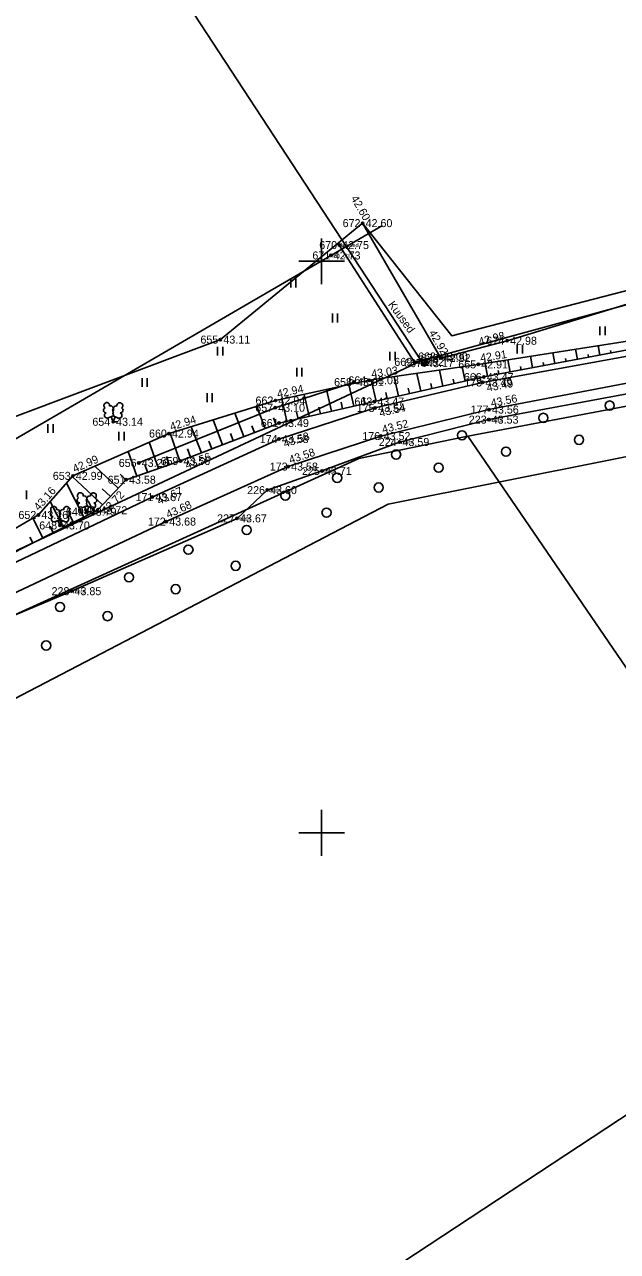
# Model space of a CAD drawing. Extents: x 505800 to 507326, y 6540058 to 6542128.
# Drawn here: x 506424 to 506475.9, y 6540313.4 to 6540420.7 of the extents above; entities that cross this region are included whole.
import ezdxf

# ---------------------------------------------------------------- set-up
doc = ezdxf.new("R2010")
doc.units = 0
for name, color, linetype in [('AED', 7, 'Continuous'), ('HALJASTUS', 7, 'Continuous'), ('KORGUS-EH2000', 7, 'Continuous'), ('MAAMUDEL', 7, 'Continuous'), ('MOOTKORG-EH2000', 7, 'Continuous'), ('MOOTMPUNKT', 7, 'Continuous'), ('MOOTNR', 7, 'Continuous'), ('MOOTPIIR', 7, 'Continuous'), ('MPOHULIIN', 7, 'Continuous'), ('PIIR', 7, 'Continuous'), ('POST', 7, 'Continuous'), ('PUU', 7, 'Continuous'), ('RELJEEF', 7, 'Continuous'), ('TEE', 7, 'Continuous'), ('VORK', 7, 'Continuous')]:
    doc.layers.add(name, color=color, linetype=linetype)

msp = doc.modelspace()

# ---------------------------------------------------------------- linework, layer by layer
at = {"layer": 'AED'}
msp.add_lwpolyline([(506555.48, 6540425.13), (506557.14, 6540420.8), (506466.24, 6540393.05), (506460.43, 6540391.54), (506453.59, 6540403.33)], dxfattribs=at)
at = {"layer": 'HALJASTUS'}
for p, q in [((506447.3, 6540398.46), (506447.3, 6540397.7)), ((506447.75, 6540398.46), (506447.75, 6540397.7)), ((506450.94, 6540395.42), (506450.94, 6540394.65)), ((506451.39, 6540395.42), (506451.39, 6540394.65)), ((506474.36, 6540394.29), (506474.36, 6540393.53)), ((506474.82, 6540394.29), (506474.82, 6540393.53)), ((506440.89, 6540392.53), (506440.89, 6540391.77)), ((506441.35, 6540392.53), (506441.35, 6540391.77)), ((506467.11, 6540392.69), (506467.11, 6540391.93)), ((506467.57, 6540392.69), (506467.57, 6540391.93)), ((506455.98, 6540392.09), (506455.98, 6540391.33)), ((506456.44, 6540392.09), (506456.44, 6540391.33)), ((506447.82, 6540390.69), (506447.82, 6540389.93)), ((506448.27, 6540390.69), (506448.27, 6540389.93)), ((506434.28, 6540389.77), (506434.28, 6540389.01)), ((506434.74, 6540389.77), (506434.74, 6540389.01)), ((506439.97, 6540388.45), (506439.97, 6540387.68)), ((506440.42, 6540388.45), (506440.42, 6540387.68)), ((506426.04, 6540385.76), (506426.04, 6540385)), ((506426.49, 6540385.76), (506426.49, 6540385)), ((506432.24, 6540385.08), (506432.24, 6540384.32)), ((506432.7, 6540385.08), (506432.7, 6540384.32)), ((506424.17, 6540379.95), (506424.17, 6540379.19))]:
    msp.add_line(p, q, dxfattribs=at)
for points in [[(506413.94, 6540356.96), (506411.03, 6540361.54), (506411.48, 6540364.07), (506416.66, 6540366.32), (506428.11, 6540371.14), (506442.6, 6540377.51), (506445.23, 6540379.98), (506450.03, 6540381.66), (506456.82, 6540384.19), (506464.63, 6540386.15), (506480.51, 6540389.11), (506500.86, 6540392.97), (506504.84, 6540391.73), (506512.52, 6540393.4), (506515.37, 6540396.65), (506532.17, 6540402.94), (506544.15, 6540408.03), (506554.03, 6540411.41), (506558.08, 6540412.38), (506561.96, 6540411.87), (506565.62, 6540410.41), (506569.33, 6540407.84)], [(506451.54, 6540401.42), (506458.11, 6540391.2), (506460.19, 6540391.67)], [(506452.84, 6540389.43), (506445.94, 6540387.19), (506433.99, 6540382.36)]]:
    msp.add_lwpolyline(points, dxfattribs=at)
for centre in [(506475.22, 6540387.38), (506469.41, 6540386.3), (506462.29, 6540384.78), (506472.53, 6540384.38), (506456.52, 6540383.1), (506466.13, 6540383.34), (506460.24, 6540381.94), (506451.36, 6540381.06), (506446.83, 6540379.49), (506455, 6540380.21), (506450.43, 6540378.01), (506443.43, 6540376.49), (506438.34, 6540374.77), (506442.47, 6540373.36), (506433.14, 6540372.36), (506437.22, 6540371.32), (506427.09, 6540369.76), (506431.26, 6540368.96), (506425.89, 6540366.39)]:
    msp.add_circle(centre, 0.4, dxfattribs=at)
at = {"layer": 'KORGUS-EH2000'}
for centre in [(506453.59, 6540403.33), (506451.54, 6540401.42), (506450.8, 6540400.51), (506441.14, 6540393.15), (506466.24, 6540393.05), (506460.19, 6540391.67), (506460.43, 6540391.54), (506458.11, 6540391.2), (506458.97, 6540391.09), (506463.71, 6540390.98), (506452.84, 6540389.43), (506454.16, 6540389.59), (506464.09, 6540389.4), (506464.2, 6540389.88), (506445.94, 6540387.19), (506445.96, 6540387.82), (506454.62, 6540387.73), (506454.68, 6540387.17), (506464.63, 6540386.15), (506464.65, 6540387.03), (506431.75, 6540385.96), (506436.64, 6540384.93), (506446.28, 6540385.85), (506446.26, 6540384.45), (506455.17, 6540384.71), (506456.82, 6540384.19), (506433.99, 6540382.36), (506437.65, 6540382.53), (506447.07, 6540382.04), (506428.22, 6540381.23), (506432.88, 6540380.89), (506450.03, 6540381.66), (506445.23, 6540379.98), (506435.18, 6540379.37), (506425.21, 6540377.81), (506429.44, 6540378.09), (506430.38, 6540378.22), (506442.6, 6540377.51), (506427.1, 6540376.89), (506436.4, 6540377.23), (506428.11, 6540371.14)]:
    msp.add_circle(centre, 0.1, dxfattribs=at)
at = {"layer": 'MOOTMPUNKT'}
for centre in [(506453.59, 6540403.33), (506451.54, 6540401.42), (506450.8, 6540400.51), (506441.14, 6540393.15), (506466.24, 6540393.05), (506460.19, 6540391.67), (506460.43, 6540391.54), (506458.11, 6540391.2), (506458.97, 6540391.09), (506463.71, 6540390.98), (506452.84, 6540389.43), (506454.16, 6540389.59), (506464.09, 6540389.4), (506464.2, 6540389.88), (506445.94, 6540387.19), (506445.96, 6540387.82), (506454.62, 6540387.73), (506454.68, 6540387.17), (506464.63, 6540386.15), (506464.65, 6540387.03), (506431.75, 6540385.96), (506436.64, 6540384.93), (506446.28, 6540385.85), (506446.26, 6540384.45), (506455.17, 6540384.71), (506456.82, 6540384.19), (506433.99, 6540382.36), (506437.65, 6540382.53), (506447.07, 6540382.04), (506428.22, 6540381.23), (506432.88, 6540380.89), (506450.03, 6540381.66), (506445.23, 6540379.98), (506435.18, 6540379.37), (506425.21, 6540377.81), (506429.44, 6540378.09), (506430.38, 6540378.22), (506442.6, 6540377.51), (506427.1, 6540376.89), (506436.4, 6540377.23), (506428.11, 6540371.14)]:
    msp.add_circle(centre, 0.1, dxfattribs=at)
at = {"layer": 'MOOTPIIR'}
for points in [[(506240.25, 6540270.96), (506245.95, 6540263.86), (506266.13, 6540270.79), (506275.98, 6540276.68), (506285.51, 6540285.66), (506298.84, 6540299.88), (506301.09, 6540304.53), (506297.72, 6540312.74), (506305.02, 6540318.44), (506309.38, 6540311.75), (506312.33, 6540315.18), (506338.03, 6540330.65), (506336.91, 6540340.18), (506347.36, 6540347.55), (506370.89, 6540361.7), (506382.39, 6540366.46), (506390.08, 6540368.87), (506400.57, 6540374.13), (506410.57, 6540381.71), (506441.14, 6540393.15), (506453.59, 6540403.33), (506461.4, 6540393.47), (506495.45, 6540402.28)], [(506495.18, 6540386.6), (506455.81, 6540378.75), (506413.94, 6540356.96), (506411.43, 6540354.11), (506402.31, 6540351.52), (506392, 6540341.5), (506380.9, 6540334.94), (506360.25, 6540322.57), (506353.01, 6540324.95), (506332.13, 6540309.04), (506315.6, 6540297.89), (506301.38, 6540281.9), (506292.83, 6540267.67), (506286.65, 6540264.51), (506248.47, 6540250.07)]]:
    msp.add_lwpolyline(points, dxfattribs=at)
at = {"layer": 'MPOHULIIN'}
msp.add_line((506416.45, 6540380.54), (506455.33, 6540403.12), dxfattribs=at)
at = {"layer": 'PIIR'}
for points in [[(506527.76, 6540505.12), (506563.96, 6540420.02), (506458.7, 6540391.28), (506429.21, 6540436.36), (506427.6, 6540438.79), (506466.35, 6540463.04), (506513.09, 6540491.84), (506518.32, 6540495.02), (506520.1, 6540496.45)], [(506326.14, 6540370.11), (506324.04, 6540375.18), (506354.05, 6540393.57), (506395.54, 6540418.74), (506427.6, 6540438.79), (506429.21, 6540436.36), (506458.7, 6540391.28), (506340.34, 6540335.82)], [(506462.8, 6540384.69), (506497.85, 6540391.32), (506509.27, 6540394.46), (506551.97, 6540410.35), (506558.26, 6540412.17), (506562.23, 6540412.5), (506566.7, 6540411.34), (506570.51, 6540407.87), (506575.14, 6540401.74), (506580.6, 6540391.81), (506495.14, 6540337.45)]]:
    msp.add_lwpolyline(points, close=True, dxfattribs=at)
for points in [[(506215.95, 6540254.34), (506268.55, 6540273.9), (506274.54, 6540277.85), (506304.35, 6540308.95), (506340.34, 6540335.82), (506458.7, 6540391.28), (506563.96, 6540420.02)], [(506497.85, 6540391.32), (506462.8, 6540384.69), (506453.27, 6540382.76), (506413.82, 6540364.84), (506374.55, 6540342.6), (506353.59, 6540332.53), (506318.07, 6540309.28), (506308, 6540301.95), (506281.65, 6540275.05), (506272.39, 6540267.75), (506224.13, 6540249.92)], [(506224.13, 6540249.92), (506272.39, 6540267.75), (506281.65, 6540275.05), (506308, 6540301.95), (506318.07, 6540309.28), (506353.59, 6540332.53), (506374.55, 6540342.6), (506413.82, 6540364.84), (506453.27, 6540382.76), (506462.8, 6540384.69), (506495.14, 6540337.45), (506342.85, 6540237.27), (506260.72, 6540195.9), (506215.68, 6540179.69)]]:
    msp.add_lwpolyline(points, dxfattribs=at)
at = {"layer": 'POST'}
msp.add_line((506458.79, 6540390.91), (506459.15, 6540391.27), dxfattribs=at)
msp.add_circle((506458.97, 6540391.09), 0.25, dxfattribs=at)
for radius, start, end in [(0.225, 224.8541, 45.0356), (0.2, 224.8427, 45.047), (0.175, 224.8281, 45.0616), (0.15, 224.8087, 45.081), (0.125, 224.7814, 45.1083), (0.1, 224.7406, 45.1491), (0.075, 224.6725, 45.2172), (0.05, 224.5363, 45.3534), (0.025, 224.1278, 45.7619)]:
    msp.add_arc((506458.97, 6540391.09), radius, start, end, dxfattribs=at)
at = {"layer": 'PUU'}
for p, q in [((506431.31, 6540386.3), (506431.75, 6540386.47)), ((506431.75, 6540385.96), (506431.57, 6540386.4)), ((506431.75, 6540386.47), (506432.19, 6540386.29)), ((506431.75, 6540385.96), (506431.93, 6540386.4)), ((506432.13, 6540385.96), (506431.75, 6540385.96)), ((506429, 6540378.42), (506429.45, 6540378.6)), ((506429.45, 6540378.6), (506429.89, 6540378.42)), ((506429.44, 6540378.09), (506429.27, 6540378.53)), ((506429.44, 6540378.09), (506429.62, 6540378.53)), ((506429.82, 6540378.09), (506429.44, 6540378.09)), ((506426.66, 6540377.22), (506427.1, 6540377.4)), ((506427.1, 6540376.89), (506426.92, 6540377.33)), ((506427.1, 6540377.4), (506427.54, 6540377.22)), ((506427.1, 6540376.89), (506427.28, 6540377.33)), ((506427.48, 6540376.89), (506427.1, 6540376.89))]:
    msp.add_line(p, q, dxfattribs=at)
for points in [[(506431.75, 6540386.97), (506431.73, 6540386.89), (506431.73, 6540386.87), (506431.74, 6540386.84), (506431.76, 6540386.81), (506431.77, 6540386.79), (506431.75, 6540386.75), (506431.73, 6540386.7), (506431.72, 6540386.68), (506431.73, 6540386.66), (506431.74, 6540386.63), (506431.77, 6540386.57), (506431.78, 6540386.55), (506431.77, 6540386.53), (506431.76, 6540386.5), (506431.75, 6540386.47)], [(506429.45, 6540379.09), (506429.43, 6540379.02), (506429.43, 6540379), (506429.44, 6540378.97), (506429.46, 6540378.93), (506429.46, 6540378.91), (506429.45, 6540378.88), (506429.42, 6540378.83), (506429.42, 6540378.8), (506429.42, 6540378.79), (506429.43, 6540378.76), (506429.47, 6540378.7), (506429.47, 6540378.68), (506429.47, 6540378.66), (506429.45, 6540378.62), (506429.45, 6540378.6)], [(506427.1, 6540377.89), (506427.08, 6540377.82), (506427.08, 6540377.8), (506427.09, 6540377.77), (506427.11, 6540377.73), (506427.12, 6540377.71), (506427.1, 6540377.68), (506427.08, 6540377.63), (506427.07, 6540377.6), (506427.08, 6540377.59), (506427.09, 6540377.56), (506427.12, 6540377.5), (506427.13, 6540377.48), (506427.12, 6540377.46), (506427.11, 6540377.42), (506427.1, 6540377.4)]]:
    msp.add_lwpolyline(points, dxfattribs=at)
for centre, radius, start, end in [((506431.12, 6540386.97), 0.224, 111.4304, 274.4987), ((506431.19, 6540387.38), 0.256, 111.5027, 232.5173), ((506431.19, 6540387.38), 0.256, 350.4856, 111.5002), ((506431.52, 6540387.13), 0.224, 308.5041, 111.5725), ((506431.99, 6540387.12), 0.225, 67.7016, 230.5126), ((506432.33, 6540387.37), 0.256, 67.6168, 188.6314), ((506432.39, 6540386.96), 0.224, 264.6183, 67.6866), ((506432.33, 6540387.37), 0.256, 306.5997, 67.6143), ((506431.22, 6540386.52), 0.237, 111.5014, 291.5004), ((506431.75, 6540386.73), 0.237, 66.7655, 111.5015), ((506432.28, 6540386.51), 0.237, 247.6166, 67.6155), ((506428.88, 6540379.5), 0.256, 111.5027, 232.5173), ((506428.88, 6540379.5), 0.256, 350.4856, 111.5002), ((506430.02, 6540379.49), 0.256, 67.6168, 188.6314), ((506430.02, 6540379.49), 0.256, 306.5997, 67.6143), ((506428.81, 6540379.09), 0.224, 111.4304, 274.4987), ((506428.91, 6540378.65), 0.237, 111.5014, 291.5004), ((506429.22, 6540379.25), 0.224, 308.5041, 111.5725), ((506429.45, 6540378.86), 0.237, 66.7655, 111.5015), ((506429.68, 6540379.25), 0.225, 67.7016, 230.5126), ((506429.98, 6540378.64), 0.237, 247.6166, 67.6155), ((506430.09, 6540379.08), 0.224, 264.6183, 67.6866), ((506426.47, 6540377.89), 0.224, 111.4304, 274.4987), ((506426.54, 6540378.3), 0.256, 111.5027, 232.5173), ((506426.57, 6540377.44), 0.237, 111.5014, 291.5004), ((506426.54, 6540378.3), 0.256, 350.4856, 111.5002), ((506426.87, 6540378.05), 0.224, 308.5041, 111.5725), ((506427.1, 6540377.65), 0.237, 66.7655, 111.5015), ((506427.34, 6540378.05), 0.225, 67.7016, 230.5126), ((506427.68, 6540378.29), 0.256, 67.6168, 188.6314), ((506427.63, 6540377.44), 0.237, 247.6166, 67.6155), ((506427.74, 6540377.88), 0.224, 264.6183, 67.6866), ((506427.68, 6540378.29), 0.256, 306.5997, 67.6143)]:
    msp.add_arc(centre, radius, start, end, dxfattribs=at)
at = {"layer": 'RELJEEF'}
for p, q in [((506474.35, 6540391.79), (506474.2, 6540392.62)), ((506468.46, 6540390.68), (506468.27, 6540391.69)), ((506470.42, 6540391.05), (506470.24, 6540392)), ((506471.41, 6540391.23), (506471.35, 6540391.51)), ((506472.39, 6540391.42), (506472.22, 6540392.31)), ((506473.37, 6540391.6), (506473.32, 6540391.86)), ((506475.34, 6540391.97), (506475.29, 6540392.21)), ((506460.62, 6540389.08), (506460.31, 6540390.48)), ((506462.57, 6540389.51), (506462.29, 6540390.77)), ((506464.53, 6540389.94), (506464.31, 6540391.07)), ((506465.51, 6540390.12), (506465.45, 6540390.45)), ((506466.49, 6540390.31), (506466.29, 6540391.38)), ((506467.48, 6540390.49), (506467.42, 6540390.81)), ((506469.44, 6540390.86), (506469.39, 6540391.16)), ((506454.77, 6540387.76), (506454.35, 6540389.62)), ((506456.72, 6540388.2), (506456.34, 6540389.9)), ((506458.67, 6540388.64), (506458.32, 6540390.19)), ((506461.6, 6540389.29), (506461.51, 6540389.69)), ((506463.55, 6540389.73), (506463.47, 6540390.09)), ((506448.91, 6540386.44), (506448.48, 6540388.36)), ((506450.87, 6540386.88), (506450.44, 6540388.78)), ((506452.82, 6540387.32), (506452.39, 6540389.21)), ((506455.74, 6540387.98), (506455.62, 6540388.51)), ((506457.69, 6540388.42), (506457.58, 6540388.91)), ((506459.65, 6540388.86), (506459.55, 6540389.3)), ((506445.07, 6540385.38), (506444.33, 6540387.31)), ((506446.96, 6540386), (506446.53, 6540387.94)), ((506449.89, 6540386.66), (506449.76, 6540387.24)), ((506451.84, 6540387.1), (506451.71, 6540387.67)), ((506453.79, 6540387.54), (506453.66, 6540388.1)), ((506441.33, 6540383.95), (506440.5, 6540386.12)), ((506443.2, 6540384.66), (506442.41, 6540386.72)), ((506446, 6540385.74), (506445.79, 6540386.3)), ((506447.94, 6540386.22), (506447.81, 6540386.8)), ((506439.47, 6540383.23), (506438.58, 6540385.53)), ((506444.13, 6540385.02), (506443.9, 6540385.62)), ((506435.71, 6540381.86), (506434.91, 6540384.17)), ((506437.6, 6540382.52), (506436.75, 6540384.96)), ((506440.4, 6540383.59), (506440.14, 6540384.26)), ((506442.27, 6540384.31), (506442.02, 6540384.94)), ((506433.82, 6540381.21), (506433.07, 6540383.36)), ((506436.65, 6540382.19), (506436.41, 6540382.91)), ((506438.53, 6540382.87), (506438.26, 6540383.58)), ((506432.19, 6540380.15), (506430.14, 6540382.07)), ((506434.76, 6540381.54), (506434.53, 6540382.21)), ((506430.82, 6540378.69), (506428.17, 6540381.18)), ((506432.87, 6540380.88), (506432.35, 6540381.37)), ((506429.17, 6540377.61), (506427.66, 6540380.6)), ((506431.51, 6540379.42), (506430.8, 6540380.09)), ((506427.39, 6540376.71), (506426.24, 6540378.99)), ((506430.07, 6540378.06), (506429.57, 6540379.04)), ((506425.6, 6540375.81), (506424.73, 6540377.53)), ((506428.28, 6540377.16), (506427.88, 6540377.95)), ((506426.49, 6540376.26), (506426.2, 6540376.84)), ((506424.71, 6540375.36), (506424.46, 6540375.86))]:
    msp.add_line(p, q, dxfattribs=at)
for points in [[(506556.21, 6540417.53), (506548.45, 6540415.76), (506537.18, 6540411.29), (506507.09, 6540401.36), (506493.82, 6540397.46), (506479.74, 6540393.49), (506463.71, 6540390.98), (506454.16, 6540389.59), (506445.96, 6540387.82), (506436.64, 6540384.93), (506428.22, 6540381.23), (506425.21, 6540377.81), (506418.01, 6540373.61), (506396.11, 6540362.16), (506387.82, 6540357.51)], [(506556.21, 6540417.53), (506549.32, 6540414.59), (506538.05, 6540410.17), (506520.49, 6540403.75), (506508.11, 6540399.97), (506494.2, 6540395.85), (506479.73, 6540392.8), (506464.2, 6540389.88), (506454.62, 6540387.73), (506446.28, 6540385.85), (506437.65, 6540382.53), (506432.88, 6540380.89), (506430.38, 6540378.22), (506418.51, 6540372.23), (506396.69, 6540360.67), (506388.24, 6540356.07)]]:
    msp.add_lwpolyline(points, dxfattribs=at)
at = {"layer": 'TEE'}
for points in [[(506478.71, 6540392.06), (506464.09, 6540389.4), (506454.68, 6540387.17), (506446.26, 6540384.45), (506435.18, 6540379.37), (506420.09, 6540372.18), (506407.96, 6540366.23), (506394.9, 6540359.33), (506383.76, 6540352.82), (506372.65, 6540346.37), (506363.22, 6540341.99), (506352.18, 6540336.39), (506347.17, 6540333.2), (506340.9, 6540329.11), (506329.32, 6540321.24)], [(506479.17, 6540389.8), (506464.65, 6540387.03), (506455.17, 6540384.71), (506447.07, 6540382.04), (506436.4, 6540377.23), (506421.23, 6540370.08), (506409.03, 6540364.19), (506396.14, 6540357.14), (506385.13, 6540350.77), (506373.75, 6540344.27), (506364.37, 6540339.72), (506353.51, 6540334.21), (506348.48, 6540331.1), (506342.34, 6540327.06), (506330.79, 6540319.25)]]:
    msp.add_lwpolyline(points, dxfattribs=at)
at = {"layer": 'VORK'}
for p, q in [((506450, 6540402), (506450, 6540398)), ((506448, 6540400), (506452, 6540400)), ((506450, 6540352), (506450, 6540348)), ((506448, 6540350), (506452, 6540350))]:
    msp.add_line(p, q, dxfattribs=at)

# ---------------------------------------------------------------- texts
at = {"layer": 'HALJASTUS'}
msp.add_text('Kuused', height=0.7, rotation=306.087, dxfattribs=at).set_placement((506455.78, 6540396.21))
at = {"layer": 'KORGUS-EH2000'}
for s, rotation, p in [(' 42.60', 300.1252, (506452.4, 6540405.73)), (' 42.92', 300.1252, (506459.23, 6540393.97)), (' 42.98', 14.5787, (506463.58, 6540392.54)), (' 42.91', 8.9025, (506463.68, 6540391.15)), (' 43.03', 8.274, (506454.14, 6540389.76)), (' 43.49', 10.3087, (506464.25, 6540388.54)), (' 42.94', 12.167, (506445.92, 6540387.99)), (' 43.56', 10.8019, (506464.62, 6540387.2)), (' 43.54', 13.3122, (506454.88, 6540386.32)), (' 42.94', 17.2368, (506436.59, 6540385.1)), (' 43.52', 13.7456, (506455.12, 6540384.88)), (' 43.58', 17.9281, (506446.53, 6540383.62)), (' 42.99', 23.6927, (506428.15, 6540381.39)), (' 43.56', 20.9962, (506437.96, 6540381.72)), (' 43.58', 18.2698, (506447.02, 6540382.2)), (' 43.16', 48.6375, (506425.08, 6540377.93)), (' 43.72', 46.8661, (506431.01, 6540377.62)), (' 43.67', 24.6184, (506435.54, 6540378.58)), (' 43.68', 24.2351, (506436.33, 6540377.39))]:
    msp.add_text(s, height=0.7, rotation=rotation, dxfattribs=at).set_placement(p)
for s, p in [(' 43.11', (506441.14, 6540392.8)), (' 43.14', (506431.75, 6540385.61)), (' 43.53', (506464.63, 6540385.8)), (' 43.59', (506456.82, 6540383.84)), (' 43.71', (506450.03, 6540381.31)), (' 43.60', (506445.23, 6540379.63)), (' 43.67', (506442.6, 6540377.16)), (' 43.85', (506428.11, 6540370.79))]:
    msp.add_text(s, height=0.7, dxfattribs=at).set_placement(p)
at = {"layer": 'MAAMUDEL'}
for s, p in [(' kuused', (506451.54, 6540401.24)), (' mp_ohl', (506450.8, 6540400.33)), (' kuused', (506460.19, 6540391.5)), (' kuused', (506458.11, 6540391.02)), (' mets', (506464.63, 6540385.97)), (' mets', (506456.82, 6540384.02)), (' mets', (506450.03, 6540381.49)), (' mets', (506445.23, 6540379.81)), (' mets', (506442.6, 6540377.33)), (' mets', (506428.11, 6540370.96))]:
    msp.add_text(s, height=0.35, dxfattribs=at).set_placement(p)
at = {"layer": 'MOOTKORG-EH2000'}
for s, p in [(' 42.60', (506453.59, 6540402.99)), (' 42.75', (506451.54, 6540401.07)), (' 42.73', (506450.8, 6540400.16)), (' 43.11', (506441.14, 6540392.8)), (' 42.98', (506466.24, 6540392.7)), (' 42.92', (506458.11, 6540390.85)), (' 43.00', (506460.19, 6540391.32)), (' 42.92', (506460.43, 6540391.19)), (' 43.17', (506458.97, 6540390.74)), (' 42.91', (506463.71, 6540390.63)), (' 43.01', (506452.84, 6540389.08)), (' 43.03', (506454.16, 6540389.24)), (' 43.49', (506464.09, 6540389.05)), (' 43.47', (506464.2, 6540389.53)), (' 43.10', (506445.94, 6540386.84)), (' 42.94', (506445.96, 6540387.47)), (' 43.47', (506454.62, 6540387.38)), (' 43.54', (506454.68, 6540386.82)), (' 43.56', (506464.65, 6540386.68)), (' 43.14', (506431.75, 6540385.61)), (' 43.49', (506446.28, 6540385.5)), (' 43.53', (506464.63, 6540385.8)), (' 42.94', (506436.64, 6540384.58)), (' 43.52', (506455.17, 6540384.36)), (' 43.58', (506446.26, 6540384.1)), (' 43.59', (506456.82, 6540383.84)), (' 43.56', (506437.65, 6540382.18)), (' 43.26', (506433.99, 6540382.01)), (' 43.58', (506447.07, 6540381.69)), (' 43.71', (506450.03, 6540381.31)), (' 42.99', (506428.22, 6540380.88)), (' 43.58', (506432.88, 6540380.54)), (' 43.67', (506435.18, 6540379.02)), (' 43.60', (506445.23, 6540379.63)), (' 43.72', (506430.38, 6540377.87)), (' 43.16', (506425.21, 6540377.46)), (' 43.79', (506429.44, 6540377.74)), (' 43.68', (506436.4, 6540376.88)), (' 43.67', (506442.6, 6540377.16)), (' 43.70', (506427.1, 6540376.54)), (' 43.85', (506428.11, 6540370.79))]:
    msp.add_text(s, height=0.7, dxfattribs=at).set_placement(p)
at = {"layer": 'MOOTNR'}
for s, p in [('672 ', (506451.84, 6540402.99)), ('670 ', (506449.79, 6540401.07)), ('671 ', (506449.19, 6540400.16)), ('655 ', (506439.39, 6540392.8)), ('674 ', (506464.42, 6540392.7)), ('669 ', (506456.36, 6540390.85)), ('668 ', (506458.44, 6540391.32)), ('673 ', (506458.68, 6540391.19)), ('667 ', (506457.22, 6540390.74)), ('665 ', (506461.96, 6540390.63)), ('658 ', (506451.09, 6540389.08)), ('664 ', (506452.34, 6540389.24)), ('666 ', (506462.45, 6540389.53)), ('178 ', (506462.48, 6540389.05)), ('657 ', (506444.19, 6540386.84)), ('662 ', (506444.21, 6540387.47)), ('663 ', (506452.87, 6540387.38)), ('175 ', (506453.07, 6540386.82)), ('177 ', (506463.04, 6540386.68)), ('654 ', (506429.93, 6540385.61)), ('661 ', (506444.67, 6540385.5)), ('223 ', (506462.88, 6540385.8)), ('660 ', (506434.89, 6540384.58)), ('176 ', (506453.56, 6540384.36)), ('174 ', (506444.58, 6540384.1)), ('224 ', (506455, 6540383.84)), ('659 ', (506435.9, 6540382.18)), ('656 ', (506432.24, 6540382.01)), ('173 ', (506445.46, 6540381.69)), ('225 ', (506448.28, 6540381.31)), ('653 ', (506426.47, 6540380.88)), ('651 ', (506431.27, 6540380.54)), ('171 ', (506433.71, 6540379.02)), ('226 ', (506443.48, 6540379.63)), ('650 ', (506428.63, 6540377.87)), ('652 ', (506423.46, 6540377.46)), ('649 ', (506427.62, 6540377.74)), ('172 ', (506434.79, 6540376.88)), ('227 ', (506440.85, 6540377.16)), ('648 ', (506425.28, 6540376.54)), ('228 ', (506426.36, 6540370.79))]:
    msp.add_text(s, height=0.7, dxfattribs=at).set_placement(p)

doc.saveas('drawing.dxf')
